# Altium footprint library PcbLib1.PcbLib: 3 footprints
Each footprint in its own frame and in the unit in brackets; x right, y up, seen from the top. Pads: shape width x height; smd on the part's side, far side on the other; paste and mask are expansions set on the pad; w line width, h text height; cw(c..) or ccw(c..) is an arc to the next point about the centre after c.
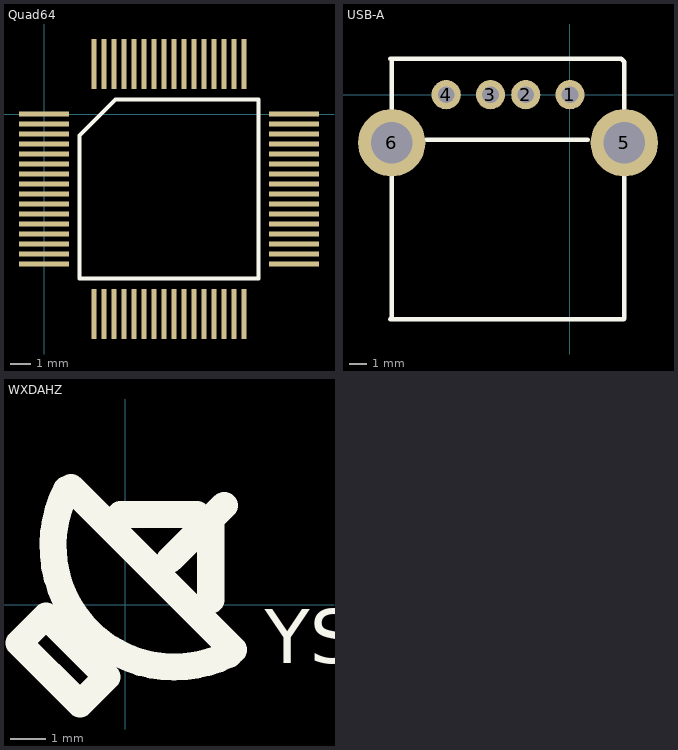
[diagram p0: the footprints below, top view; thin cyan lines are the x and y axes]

## Quad64 [mm]
pads (64):
  rect 2.5x0.25 smd: 1(0,0) 2(0,-0.5) 3(0,-1) 4(0,-1.5) 5(0,-2) 6(0,-2.5) 7(0,-3) 8(0,-3.5) 9(0,-4) 10(0,-4.5) 11(0,-5) 12(0,-5.5) 13(0,-6) 14(0,-6.5) 15(0,-7) 16(0,-7.5) 33(12.5,-7.5) 34(12.5,-7) 35(12.5,-6.5) 36(12.5,-6) 37(12.5,-5.5) 38(12.5,-5) 39(12.5,-4.5) 40(12.5,-4) 41(12.5,-3.5) 42(12.5,-3) 43(12.5,-2.5) 44(12.5,-2) 45(12.5,-1.5) 46(12.5,-1) 47(12.5,-0.5) 48(12.5,0)
  rect 0.25x2.5 smd: 17(2.5,-10) 18(3,-10) 19(3.5,-10) 20(4,-10) 21(4.5,-10) 22(5,-10) 23(5.5,-10) 24(6,-10) 25(6.5,-10) 26(7,-10) 27(7.5,-10) 28(8,-10) 29(8.5,-10) 30(9,-10) 31(9.5,-10) 32(10,-10) 49(10,2.5) 50(9.5,2.5) 51(9,2.5) 52(8.5,2.5) 53(8,2.5) 54(7.5,2.5) 55(7,2.5) 56(6.5,2.5) 57(6,2.5) 58(5.5,2.5) 59(5,2.5) 60(4.5,2.5) 61(4,2.5) 62(3.5,2.5) 63(3,2.5) 64(2.5,2.5)
Top Overlay:
  lines w0.2: 1.785,-8.215 10.715,-8.215 10.715,0.715 3.57,0.715 1.785,-1.07 1.785,-8.215

## USB-A [mil]
pads (6):
  round 65 hole 37: 1(0,0) 2(-98.5,0) 3(-177,0) 4(-275.6,0)
  round 150 hole 93: 5(121,-107) 6(-397,-107)
Top Overlay:
  lines w10: -400,80 114,80 121,73 121,-107 121,-499 120,-500 -400,-500 -397,-497 -397,-477 -397,-107 -397,77 ; -320,-100 40,-100

## WXDAHZ [mm]
Top Overlay:
  lines w0.762: -1.64,3.243 ccw(c1.392,1.662) 2.921,-1.397 ; -1.524,3.302 3.048,-1.27 ; -0.127,2.54 2.032,2.54 ; 1.27,1.27 2.794,2.794 ; 2.413,0.127 2.413,2.286 ; -2.984,-1.079 -1.27,-2.794 -0.508,-2.032 -2.222,-0.318 -2.984,-1.079
  text "YSUWUXIE" at 3.937,-1.651 h1.52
